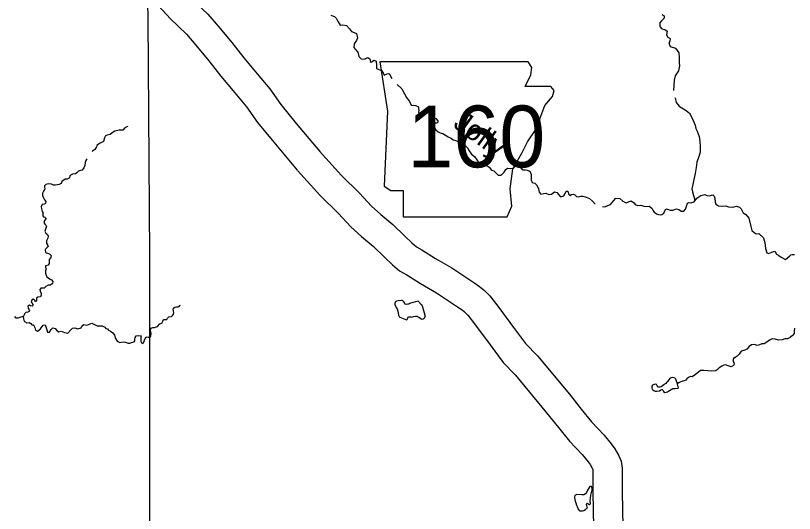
# Model space of a CAD drawing. Extents: x -492261 to -432772, y 1441225 to 1452922.
# Drawn here: x -459493.5 to -459293.9, y 1451964 to 1452091.7 of the extents above; entities that cross this region are included whole.
import ezdxf

# ---------------------------------------------------------------- set-up
doc = ezdxf.new("R2010")
doc.units = 0
doc.layers.add('Default', color=7, linetype='Continuous')

msp = doc.modelspace()

# ---------------------------------------------------------------- linework, layer by layer
at = {"layer": 'Default'}
for points in [[(-459468.79, 1452127.67), (-459459.98, 1452111.99), (-459458.52, 1452108.9), (-459457.15, 1452106.19), (-459456.64, 1452105.38), (-459455.04, 1452103.48), (-459453.3, 1452101.43), (-459448.46, 1452096.09), (-459444.29, 1452092.09), (-459441.62, 1452088.99), (-459438.12, 1452084.79), (-459435.07, 1452080.88), (-459431.6, 1452076.72), (-459428.4, 1452072.88), (-459425.54, 1452068.86), (-459421.59, 1452064.05), (-459415.57, 1452056.87)], [(-459475.33, 1452124), (-459466.65, 1452108.55), (-459465.26, 1452105.61), (-459463.7, 1452102.51), (-459462.72, 1452100.94), (-459460.76, 1452098.64), (-459458.94, 1452096.48), (-459453.84, 1452090.86), (-459449.74, 1452086.92), (-459447.34, 1452084.14), (-459443.96, 1452080.08), (-459440.91, 1452076.17), (-459437.36, 1452071.92), (-459434.35, 1452068.3), (-459431.5, 1452064.3), (-459427.36, 1452059.26), (-459421.32, 1452052.05)], [(-459458.21, 1451893.09), (-459458.24, 1451898.09), (-459459.09, 1451959.74), (-459459.15, 1451963.72), (-459459.13, 1452025.76), (-459459.1, 1452030.09), (-459459.57, 1452090.97), (-459459.6, 1452094.87)], [(-459412.69, 1452091.77), (-459412.26, 1452091.59), (-459411.79, 1452091.44), (-459411.36, 1452091.05), (-459411.16, 1452090.71), (-459410.82, 1452090.06), (-459410.3, 1452089.27), (-459409.66, 1452089.33), (-459408.75, 1452089.19), (-459407.9, 1452088.27), (-459407.39, 1452087.62), (-459406.76, 1452087.35), (-459406.13, 1452087.06), (-459405.85, 1452086.02), (-459406.16, 1452085.3), (-459406.73, 1452084.41), (-459406.82, 1452083.55), (-459406.41, 1452082.99), (-459405.84, 1452082.27), (-459405.54, 1452081.18), (-459404.97, 1452080.58), (-459404.03, 1452080.48), (-459403.91, 1452080.62), (-459403.26, 1452080.98), (-459402.77, 1452080.59), (-459402.52, 1452079.77), (-459402.18, 1452079.81), (-459401.74, 1452080.27), (-459401.13, 1452080.04), (-459400.98, 1452078.87), (-459400.99, 1452078.14), (-459400.43, 1452077.84), (-459399.61, 1452077.54), (-459399.04, 1452076.42), (-459398.25, 1452076.77), (-459397.8, 1452076.8), (-459397.09, 1452075.55)], [(-459327.8, 1452092), (-459327.3, 1452091.59), (-459327.3, 1452091.02), (-459327.92, 1452090.37), (-459328.38, 1452089.85), (-459328.4, 1452088.92), (-459327.87, 1452088.27), (-459327.1, 1452088.16), (-459326.48, 1452087.66), (-459326.66, 1452086.73), (-459326.33, 1452086.18), (-459325.71, 1452085.85), (-459325.85, 1452085.16), (-459326.1, 1452084.68), (-459325.73, 1452083.77), (-459324.4, 1452083.38), (-459323.54, 1452082.17), (-459323.47, 1452080.95), (-459323.42, 1452079.56), (-459323.36, 1452078.78), (-459323.64, 1452077.56)], [(-459323.64, 1452077.56), (-459324.44, 1452076.26), (-459324.69, 1452075.14), (-459324.85, 1452072.48)], [(-459395.73, 1452074.02), (-459394.56, 1452072.95), (-459393.87, 1452071.63), (-459393.35, 1452070.72), (-459392.57, 1452069.63), (-459392.13, 1452068.76), (-459391.05, 1452068.67), (-459390.37, 1452068.35), (-459390.21, 1452067.45), (-459390.23, 1452066.89), (-459389.78, 1452066.39), (-459388.96, 1452066.91), (-459388.5, 1452067.23), (-459387.97, 1452067.17), (-459387.58, 1452066.79), (-459387.21, 1452065.95), (-459386.64, 1452065.67), (-459385.79, 1452065.31), (-459385.27, 1452064.68), (-459385.33, 1452064.36), (-459385.55, 1452064.13), (-459386.18, 1452064.11), (-459386.57, 1452064.2), (-459387.01, 1452064.05), (-459387.04, 1452063.57), (-459386.55, 1452063.36), (-459386.12, 1452063.09), (-459385.81, 1452062.43), (-459385.2, 1452061.9), (-459384.7, 1452061.63), (-459384.03, 1452061.47), (-459383.36, 1452060.99), (-459382.69, 1452060.56), (-459381.89, 1452060.29), (-459381.37, 1452059.84), (-459380.93, 1452059.79), (-459379.78, 1452059.22), (-459379.27, 1452058.62), (-459378.24, 1452058.27), (-459377.66, 1452057.76), (-459377.26, 1452057.03), (-459376.64, 1452056.18), (-459375.88, 1452055.52), (-459375.27, 1452054.74), (-459374.74, 1452053.81), (-459373.95, 1452053.15), (-459372.89, 1452053.36), (-459372.13, 1452052.82), (-459371.54, 1452052.09), (-459370.93, 1452051.85)], [(-459324.49, 1452070.57), (-459324.18, 1452069.43), (-459323.42, 1452068.48), (-459321.64, 1452067.34), (-459320.82, 1452066.64), (-459320.06, 1452065.37), (-459319.37, 1452063.59), (-459319.17, 1452062.77), (-459318.83, 1452062.05), (-459318.29, 1452060.72), (-459318.1, 1452059.39), (-459318.03, 1452058.04), (-459318.02, 1452056.71), (-459318.42, 1452055.54), (-459318.9, 1452054.11), (-459319.05, 1452052.77), (-459319.33, 1452051.2), (-459319.67, 1452049.69), (-459319.96, 1452048.37), (-459320.15, 1452047.26), (-459320.02, 1452046.46), (-459319.73, 1452045.6), (-459319.59, 1452045.06), (-459319.5, 1452044.59), (-459319.39, 1452044.19)], [(-459464.74, 1452063.22), (-459465.01, 1452063.17), (-459465.54, 1452062.88), (-459466.06, 1452062.33), (-459467.03, 1452062.3), (-459468.11, 1452062.02), (-459468.75, 1452061.64), (-459469.29, 1452061.17), (-459470.05, 1452061.07), (-459470.5, 1452060.82), (-459470.73, 1452060.32), (-459471.01, 1452059.42), (-459472.03, 1452058.9), (-459472.68, 1452058.38), (-459472.81, 1452058.06), (-459473.19, 1452057.32), (-459473.79, 1452056.91), (-459473.91, 1452056.78)], [(-459415.67, 1452056.97), (-459410.03, 1452050.73), (-459405.37, 1452046.18), (-459402.33, 1452042.86), (-459399.93, 1452040.73), (-459396.87, 1452038.1), (-459393.78, 1452035.14), (-459391.92, 1452033.42), (-459390.74, 1452032.4), (-459389.38, 1452031.59), (-459385.86, 1452029.41), (-459381.7, 1452027.01), (-459377.85, 1452024.47), (-459376.06, 1452023.24), (-459374.58, 1452022.26), (-459373.37, 1452021.24), (-459371.96, 1452019.83), (-459369.69, 1452016.85), (-459365.87, 1452011.72), (-459362.8, 1452007.58), (-459359.78, 1452004.47), (-459351.58, 1451994.58), (-459348.56, 1451990.79), (-459345.88, 1451987.51), (-459342.67, 1451984.11), (-459340.87, 1451981.9), (-459339.89, 1451980.58), (-459339.02, 1451978.96), (-459338.31, 1451977.4), (-459338.07, 1451975.61), (-459338.06, 1451969.61), (-459337.61, 1451946.95)], [(-459475.32, 1452054.92), (-459475.56, 1452054.56), (-459475.7, 1452054), (-459475.83, 1452053.29), (-459476.04, 1452052.62), (-459476.46, 1452052.09), (-459476.93, 1452051.96), (-459477.44, 1452051.77), (-459477.86, 1452051.34), (-459478.16, 1452051.13), (-459478.96, 1452051.06), (-459479.54, 1452050.71), (-459479.84, 1452050.02), (-459480.28, 1452049.72), (-459480.84, 1452049.72), (-459481.67, 1452049.12), (-459481.9, 1452048.64), (-459482.36, 1452048.42), (-459482.78, 1452048.29), (-459483.31, 1452048.24), (-459483.83, 1452048.25), (-459484.35, 1452048.47), (-459485.07, 1452048.57), (-459485.78, 1452048.42), (-459486.12, 1452048.05), (-459486.12, 1452047.57), (-459486.08, 1452047.43), (-459486.09, 1452047.06), (-459486.38, 1452046.67), (-459486.63, 1452046.19), (-459486.63, 1452045.59), (-459486.41, 1452044.92), (-459486.24, 1452044.61), (-459486.1, 1452044.43), (-459485.83, 1452044.05), (-459485.9, 1452043.47), (-459486.19, 1452043.3), (-459486.72, 1452043.21), (-459486.98, 1452042.62), (-459486.94, 1452042.12), (-459486.69, 1452041.43), (-459486.58, 1452041.21), (-459486.58, 1452040.81), (-459486.57, 1452040.34), (-459486.42, 1452040.12), (-459486.03, 1452040.01), (-459485.72, 1452039.69), (-459486.12, 1452039.15), (-459486.3, 1452038.66), (-459486.03, 1452038.21), (-459485.77, 1452037.99), (-459485.64, 1452037.6), (-459485.83, 1452037.16), (-459486.07, 1452036.42), (-459485.83, 1452035.9), (-459485.4, 1452035.57), (-459485.18, 1452035.16), (-459485.31, 1452034.59), (-459485.63, 1452033.97), (-459485.62, 1452033.37), (-459485.36, 1452032.95), (-459485.21, 1452032.49), (-459485.51, 1452032.1), (-459485.95, 1452031.69), (-459485.86, 1452030.99), (-459485.72, 1452030.87), (-459485.34, 1452030.8), (-459484.87, 1452030.6), (-459484.46, 1452030.16), (-459484.49, 1452029.7), (-459484.94, 1452029.17), (-459484.94, 1452028.68), (-459484.92, 1452028.09), (-459485.16, 1452027.7), (-459485.9, 1452027.5), (-459485.88, 1452027.06)], [(-459370.93, 1452051.85), (-459370.46, 1452051.36), (-459369.87, 1452050.78), (-459369.1, 1452050.79), (-459368.32, 1452051.54), (-459367.86, 1452052.21), (-459367.4, 1452052.54), (-459366.55, 1452052.51), (-459365.94, 1452052.58), (-459365.53, 1452052.97), (-459365.17, 1452053.4), (-459364.79, 1452053.31), (-459364.29, 1452052.93), (-459363.89, 1452052.37), (-459363.38, 1452052.15), (-459362.91, 1452052.14), (-459362.41, 1452052.07), (-459361.68, 1452051.78), (-459361.33, 1452050.92), (-459361.39, 1452049.92), (-459361.35, 1452049.49), (-459361.11, 1452048.88), (-459360.46, 1452048.69), (-459359.9, 1452048.24), (-459359.5, 1452047.26), (-459359.31, 1452046.45), (-459358.89, 1452045.88), (-459358.1, 1452046.11), (-459357.61, 1452046.14), (-459356.88, 1452045.78), (-459356.16, 1452045.91), (-459355.39, 1452046.52), (-459354.78, 1452046.37), (-459354.32, 1452045.73), (-459353.82, 1452045.25), (-459353, 1452045.46), (-459352.71, 1452045.93), (-459352.39, 1452046.69), (-459351.98, 1452046.67), (-459351.74, 1452045.81), (-459351.42, 1452045.54), (-459351.06, 1452045.84), (-459350.6, 1452045.94), (-459350.15, 1452045.75), (-459349.75, 1452045.27), (-459349.29, 1452045.19), (-459348.67, 1452045.43), (-459348.09, 1452045.42), (-459347.23, 1452045.17), (-459346.42, 1452044.76), (-459345.69, 1452044.14), (-459344.93, 1452043.38)], [(-459421.23, 1452051.95), (-459415.44, 1452045.53), (-459410.76, 1452040.96), (-459407.6, 1452037.5), (-459404.86, 1452035.08), (-459401.91, 1452032.55), (-459398.92, 1452029.68), (-459396.92, 1452027.82), (-459395.13, 1452026.28), (-459393.27, 1452025.18), (-459389.71, 1452022.97), (-459385.64, 1452020.63), (-459382.04, 1452018.25), (-459380.25, 1452017.03), (-459379.08, 1452016.24), (-459378.45, 1452015.71), (-459377.63, 1452014.89), (-459375.68, 1452012.34), (-459371.89, 1452007.24), (-459368.53, 1452002.71), (-459365.36, 1451999.45), (-459357.4, 1451989.85), (-459354.39, 1451986.07), (-459351.51, 1451982.56), (-459348.31, 1451979.15), (-459346.79, 1451977.3), (-459346.25, 1451976.56), (-459345.74, 1451975.62), (-459345.59, 1451975.31), (-459345.57, 1451975.11), (-459345.56, 1451969.52), (-459345.1, 1451946.75)], [(-459343.11, 1452042.73), (-459342.6, 1452042.69), (-459341.07, 1452043.23), (-459340.16, 1452044.32), (-459339.68, 1452044.86), (-459338.64, 1452044.79), (-459337.85, 1452044.1), (-459337.05, 1452043.66), (-459335.85, 1452044.22), (-459334.95, 1452043.67), (-459334.68, 1452043.22), (-459334.15, 1452043), (-459333.27, 1452043.09), (-459332.46, 1452042.79), (-459331.79, 1452042.77), (-459331.11, 1452042.81), (-459330.46, 1452042.31), (-459330.22, 1452041.83), (-459329.84, 1452041.27), (-459329.59, 1452041.11), (-459329.21, 1452040.89), (-459328.98, 1452040.8), (-459328.77, 1452040.71), (-459328.3, 1452040.61), (-459327.9, 1452040.65), (-459327.4, 1452041.07), (-459327.11, 1452041.6), (-459326.88, 1452042), (-459326.73, 1452042.17), (-459326.42, 1452042.09), (-459325.78, 1452041.83), (-459325.04, 1452041.8), (-459324.12, 1452042.18), (-459323.55, 1452041.98), (-459322.92, 1452041.53), (-459322.24, 1452041.56), (-459321.83, 1452042.09), (-459321.26, 1452043.56), (-459320.91, 1452043.77), (-459320.4, 1452043.66), (-459319.57, 1452043.95), (-459318.86, 1452044.89), (-459317.9, 1452045.55), (-459316.85, 1452045.85), (-459316.35, 1452045.55), (-459315.71, 1452045.5), (-459314.77, 1452045.71)], [(-459314.77, 1452045.71), (-459314.45, 1452045.38), (-459314.32, 1452044.75), (-459314.24, 1452043.85), (-459313.99, 1452043.35), (-459313.31, 1452042.89), (-459312.44, 1452042.81), (-459311.48, 1452042.92), (-459310.78, 1452042.62), (-459309.71, 1452042.56), (-459308.71, 1452042.8), (-459307.97, 1452042.6), (-459307.57, 1452042.11), (-459307.01, 1452041.13), (-459306.37, 1452040.67), (-459305.58, 1452039.79), (-459305.04, 1452037.62), (-459304.79, 1452036.57), (-459304.18, 1452036.08), (-459303.65, 1452035.74), (-459303, 1452035.81), (-459301.84, 1452034.71), (-459301.49, 1452033.54), (-459301.3, 1452031.95), (-459300.96, 1452030.82), (-459300.52, 1452030.67), (-459299.66, 1452031.06), (-459298.88, 1452031.26), (-459298.5, 1452030.52), (-459297.86, 1452030.18), (-459297.24, 1452029.73), (-459296.2, 1452029.16), (-459295.02, 1452030.12), (-459294.77, 1452030.34), (-459294.46, 1452030.44), (-459293.85, 1452030.4)], [(-459485.88, 1452027.06), (-459485.7, 1452026.77), (-459485.9, 1452026.32), (-459485.9, 1452025.67), (-459485.74, 1452025.14), (-459485.49, 1452024.7), (-459484.84, 1452024.22), (-459484.3, 1452023.92), (-459483.97, 1452023.51), (-459484.08, 1452022.99), (-459484.61, 1452022.57), (-459485.19, 1452022.58), (-459485.76, 1452022.26), (-459486.19, 1452021.77), (-459486.63, 1452021.8), (-459487.09, 1452021.78), (-459487.34, 1452021.47), (-459487.22, 1452021.03), (-459487, 1452020.46), (-459487.02, 1452019.97), (-459487.13, 1452019.59), (-459487.81, 1452019.46), (-459488.2, 1452019.25), (-459488.21, 1452018.66), (-459488.19, 1452018.51), (-459488.28, 1452018.34), (-459488.45, 1452018.41), (-459488.58, 1452018.62), (-459488.69, 1452018.8), (-459489.04, 1452018.97), (-459489.41, 1452018.73), (-459489.54, 1452018.19), (-459489.34, 1452018.01), (-459489.12, 1452017.65), (-459489.14, 1452017.37), (-459489.27, 1452017.19), (-459489.7, 1452017.25), (-459490.01, 1452017.41), (-459490.44, 1452017.15), (-459490.35, 1452016.68), (-459490.12, 1452016.4), (-459489.96, 1452016), (-459490.04, 1452015.81), (-459490.43, 1452015.61), (-459490.93, 1452015.53), (-459491.19, 1452015.32), (-459491.34, 1452014.95), (-459491.51, 1452014.59), (-459491.91, 1452014.46), (-459492.43, 1452014.31), (-459492.87, 1452014.07), (-459493.36, 1452014.12), (-459493.71, 1452014.55)], [(-459491.62, 1452014.55), (-459491.54, 1452013.96), (-459491.45, 1452013.62), (-459491.29, 1452013.24), (-459490.64, 1452012.9), (-459490.02, 1452012.96), (-459489.64, 1452012.76), (-459489.34, 1452012.43), (-459488.93, 1452012.37), (-459488.65, 1452011.74), (-459488.4, 1452011.01), (-459487.92, 1452010.78), (-459487.16, 1452011.41), (-459486.45, 1452012.28), (-459485.95, 1452012.37), (-459485.5, 1452011.12), (-459485.4, 1452010.52), (-459484.86, 1452010.54), (-459484.45, 1452011.17), (-459483.96, 1452011.63), (-459483.37, 1452011.46), (-459482.91, 1452010.85), (-459482.44, 1452010.61), (-459481.89, 1452010.79), (-459481.02, 1452010.44), (-459480.13, 1452010.25), (-459479.36, 1452011.11), (-459478.92, 1452011.54), (-459478.32, 1452011.66), (-459477.57, 1452011.4), (-459476.7, 1452011.62), (-459476.53, 1452012.09), (-459476.04, 1452012.5), (-459475.32, 1452012.33), (-459474.41, 1452012.63), (-459473.97, 1452012.81), (-459473.3, 1452012.51), (-459472.62, 1452012.18), (-459471.35, 1452012.17), (-459470.64, 1452011.81), (-459470.38, 1452011.42), (-459469.96, 1452011.33), (-459469.78, 1452011.13), (-459469.23, 1452010.73), (-459468.58, 1452010.34), (-459468.15, 1452009.72), (-459467.9, 1452008.86), (-459467.5, 1452008.24), (-459466.78, 1452007.87), (-459465.95, 1452008.06), (-459465.4, 1452007.96), (-459464.72, 1452007.68), (-459464.22, 1452007.69), (-459463.83, 1452007.9), (-459463.13, 1452008.08), (-459463, 1452008.3), (-459462.98, 1452008.66), (-459462.92, 1452009.13), (-459462.63, 1452009.54), (-459461.95, 1452009.69), (-459461.37, 1452009.57), (-459461.45, 1452009.3), (-459461.42, 1452008.87), (-459461.47, 1452008.1), (-459461.26, 1452007.74), (-459460.92, 1452007.64), (-459460.64, 1452007.99), (-459460.44, 1452008.71), (-459460.03, 1452009.3), (-459459.53, 1452009.26), (-459459.06, 1452009.23), (-459458.83, 1452009.52), (-459458.78, 1452010.17), (-459458.98, 1452010.76), (-459458.88, 1452011.58), (-459458.39, 1452011.74), (-459457.93, 1452011.69), (-459457.17, 1452011.99), (-459456.58, 1452012.62), (-459456.07, 1452012.86), (-459455.82, 1452013.3), (-459455.59, 1452013.8), (-459455.11, 1452013.78), (-459454.77, 1452013.79), (-459454.61, 1452014.09), (-459454.25, 1452014.43), (-459453.61, 1452014.57), (-459453.33, 1452014.76), (-459453.06, 1452015.13), (-459453, 1452015.6), (-459453.02, 1452015.94), (-459453.13, 1452016.29), (-459453.09, 1452016.65), (-459452.73, 1452016.96), (-459452.3, 1452017.03), (-459451.83, 1452017), (-459451.57, 1452017.13), (-459451.44, 1452017.34), (-459451.23, 1452017.46)], [(-459390.35, 1452018.5), (-459392.29, 1452017.93), (-459392.8, 1452017.72), (-459392.98, 1452017.67), (-459393.39, 1452017.58), (-459393.65, 1452017.7), (-459393.83, 1452018.03), (-459394.03, 1452018.28), (-459394.17, 1452018.46), (-459394.37, 1452018.63), (-459394.61, 1452018.67), (-459395.48, 1452018.55), (-459395.88, 1452018.46), (-459396.09, 1452018.35), (-459396.2, 1452018.22), (-459396.27, 1452018.12), (-459396.34, 1452017.9), (-459396.35, 1452017.63), (-459396.17, 1452017.17), (-459395.98, 1452016.86), (-459395.74, 1452016.48), (-459395.53, 1452015.94), (-459395.46, 1452015.45), (-459395.35, 1452014.88), (-459395.2, 1452014.55), (-459395.01, 1452014.33), (-459394.63, 1452014.15), (-459393.77, 1452013.85), (-459393.37, 1452013.71), (-459393.2, 1452013.77), (-459393.09, 1452013.97), (-459392.99, 1452014.21), (-459392.91, 1452014.36), (-459392.75, 1452014.44), (-459392.38, 1452014.46), (-459392.19, 1452014.41), (-459391.92, 1452014.38), (-459391.55, 1452014.53), (-459391.06, 1452014.59), (-459390.82, 1452014.59), (-459390.58, 1452014.58), (-459390.39, 1452014.49), (-459390.15, 1452014.35), (-459389.6, 1452013.93), (-459389.38, 1452013.89), (-459388.97, 1452013.97), (-459388.77, 1452014.13), (-459388.69, 1452014.22), (-459388.53, 1452014.52)], [(-459390.35, 1452018.5), (-459389.47, 1452017.51), (-459389.34, 1452017.23), (-459388.77, 1452015.47), (-459388.53, 1452014.52)], [(-459293.86, 1452011.53), (-459293.93, 1452010.8), (-459293.95, 1452010.15), (-459294.36, 1452009.7), (-459294.93, 1452009.25), (-459295.63, 1452008.81), (-459296.3, 1452008.83), (-459297, 1452008.57), (-459298, 1452008.44), (-459298.84, 1452008.75), (-459299.53, 1452008.79), (-459299.55, 1452008.79), (-459300.31, 1452008.45), (-459301.24, 1452007.75), (-459301.68, 1452007.49), (-459302.21, 1452007.52), (-459302.86, 1452007.23), (-459303.46, 1452007.07), (-459304.09, 1452007.35), (-459304.9, 1452007.3), (-459305.47, 1452006.8), (-459306.1, 1452006.17), (-459306.57, 1452005.9), (-459307.56, 1452005.64), (-459308.01, 1452004.9), (-459308.52, 1452004.35), (-459309.06, 1452004.02), (-459309.53, 1452003.76), (-459309.63, 1452003.2), (-459309.38, 1452002.76), (-459309.3, 1452002.33), (-459309.46, 1452001.95), (-459310.09, 1452001.65), (-459310.87, 1452001.89), (-459311.55, 1452002.12), (-459312.02, 1452002.09), (-459312.49, 1452001.83), (-459313.16, 1452001.35), (-459313.61, 1452000.92), (-459314.06, 1452000.58), (-459315.09, 1452000.51), (-459316.04, 1452000.6), (-459317.08, 1452000.72), (-459317.94, 1452000.66), (-459318.46, 1452000.3), (-459319.21, 1451999.63), (-459320.06, 1451999.09), (-459320.55, 1451999.15), (-459321.04, 1451998.91), (-459321.45, 1451998.56), (-459321.76, 1451998.25), (-459322.11, 1451998.02), (-459322.51, 1451997.95), (-459322.98, 1451997.81), (-459323.26, 1451997.69), (-459323.37, 1451997.59), (-459323.55, 1451997.51), (-459323.98, 1451997.31)], [(-459324.42, 1451998.73), (-459325.17, 1451998.86), (-459325.52, 1451998.83), (-459325.7, 1451998.72), (-459325.83, 1451998.62), (-459326.12, 1451998.33), (-459326.44, 1451997.87), (-459326.56, 1451997.69), (-459326.88, 1451997.36), (-459327.32, 1451997.01), (-459327.69, 1451996.74), (-459328.06, 1451996.53), (-459328.41, 1451996.38), (-459328.86, 1451996.4), (-459328.99, 1451996.59), (-459329.09, 1451996.88), (-459329.14, 1451996.96), (-459329.25, 1451997.06), (-459329.51, 1451997.16), (-459329.87, 1451997.12), (-459330.28, 1451996.96), (-459330.44, 1451996.7), (-459330.45, 1451996.22), (-459330.36, 1451995.92), (-459330.22, 1451995.71), (-459329.96, 1451995.53), (-459329.58, 1451995.39), (-459329.15, 1451995.35), (-459328.47, 1451995.5), (-459328.14, 1451995.7), (-459327.78, 1451995.8), (-459327.57, 1451995.59), (-459327.42, 1451995.34), (-459327.07, 1451995.07), (-459326.44, 1451995.21), (-459325.95, 1451995.54), (-459325.44, 1451995.85), (-459325.09, 1451996.03), (-459324.77, 1451996.1), (-459324.47, 1451996.07), (-459323.66, 1451996.17)], [(-459324.42, 1451998.73), (-459324.06, 1451997.61), (-459323.66, 1451996.17)], [(-459345.73, 1451970.5), (-459345.83, 1451970.75), (-459345.94, 1451970.92), (-459346.11, 1451970.95), (-459346.29, 1451970.91), (-459346.49, 1451970.72), (-459347.02, 1451969.82), (-459347.21, 1451969.41), (-459347.47, 1451969.04), (-459347.87, 1451968.83), (-459348.42, 1451968.77), (-459349.68, 1451968.87), (-459350.19, 1451968.6), (-459350.23, 1451968.16), (-459350.15, 1451967.64), (-459350.05, 1451967.2), (-459349.93, 1451966.79), (-459349.72, 1451966.19), (-459349.57, 1451965.79), (-459349.29, 1451965.09), (-459349.1, 1451964.81), (-459348.92, 1451964.7), (-459348.57, 1451964.67), (-459348.17, 1451964.72), (-459347.84, 1451964.82), (-459347.46, 1451965.02), (-459347.06, 1451965.35), (-459346.93, 1451965.51), (-459347, 1451965.74), (-459347.11, 1451966.07), (-459347.15, 1451966.36), (-459347.12, 1451966.62), (-459347.02, 1451966.7), (-459346.83, 1451966.58), (-459346.6, 1451966.32), (-459346.41, 1451966.29), (-459346.24, 1451966.43), (-459346.19, 1451966.61), (-459346.23, 1451967.22), (-459346.19, 1451967.94), (-459346.09, 1451968.68), (-459345.79, 1451969.71), (-459345.75, 1451969.91), (-459345.73, 1451970.12), (-459345.72, 1451970.36), (-459345.73, 1451970.5)]]:
    msp.add_lwpolyline(points, dxfattribs=at)
msp.add_lwpolyline([(-459400.13, 1452079.86), (-459398.23, 1452067.17), (-459399.07, 1452047.92), (-459397.38, 1452046.87), (-459394.21, 1452046.87), (-459394.21, 1452040.1), (-459367.56, 1452040.1), (-459366.29, 1452042.85), (-459366.72, 1452047.29), (-459366.08, 1452052.36), (-459363.76, 1452056.38), (-459362.28, 1452059.34), (-459360.16, 1452062.52), (-459358.89, 1452065.9), (-459357.83, 1452068.65), (-459355.93, 1452070.97), (-459355.51, 1452072.45), (-459356.35, 1452073.51), (-459362.91, 1452073.51), (-459361.43, 1452076.47), (-459361.22, 1452078.38), (-459362.1, 1452079.84)], close=True, dxfattribs=at)

# ---------------------------------------------------------------- texts
msp.add_text('160', height=15.84, dxfattribs=at).set_placement((-459393.1, 1452052.78))
msp.add_text('Jolly', height=5.28, rotation=324.2114, dxfattribs=at).set_placement((-459381.66, 1452063.31))

doc.saveas('drawing.dxf')
